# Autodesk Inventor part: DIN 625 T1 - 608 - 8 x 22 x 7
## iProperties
Library Location: C:\Program Files\Autodesk\Inventor 6\content
Library: local
SubLibrary: DIN
Family: 249
Member: 20
Member Major Revision: 1
Member Minor Revision: 1
Comments: To add or edit properties for Autodesk Inventor files, use iProperties.
Created: 2004-09
Part Number: DIN 625 T1 - 608 - 8 x 22 x 7
Vendor: Autodesk Inc.
Document SubType Name: Modeling
Designer: Laurent
Description: Roulement rainuré à billes
Standard: DIN 625 T1 608 - 8 x 22 x 7
Density: 1 g/cm^3
Alert: To add or edit properties for Autodesk Inventor files, use iProperties.
Control State: 0
Master: False
Checked Out: False
Shininess: 64.0
Length Units: 11269
Angle Units: 11279
Time Units: 11290
Mass Units: 11283
Length Display Precision: 3
Angle Display Precision: 2
Compacted: True
Classification: un/spsc 31171504
Density: 0.0
Volumn: 0.0
Area: 0.0
PropertySet Name: Model Information
Author: Laurent
Revision Number: 1
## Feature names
1. Corps [Revolution]
2. Congé1 [Fillet]
3. Sphère [Revolution]
4. Sphères [Circular Pattern]
